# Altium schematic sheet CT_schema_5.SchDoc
size 479 x 328 mm
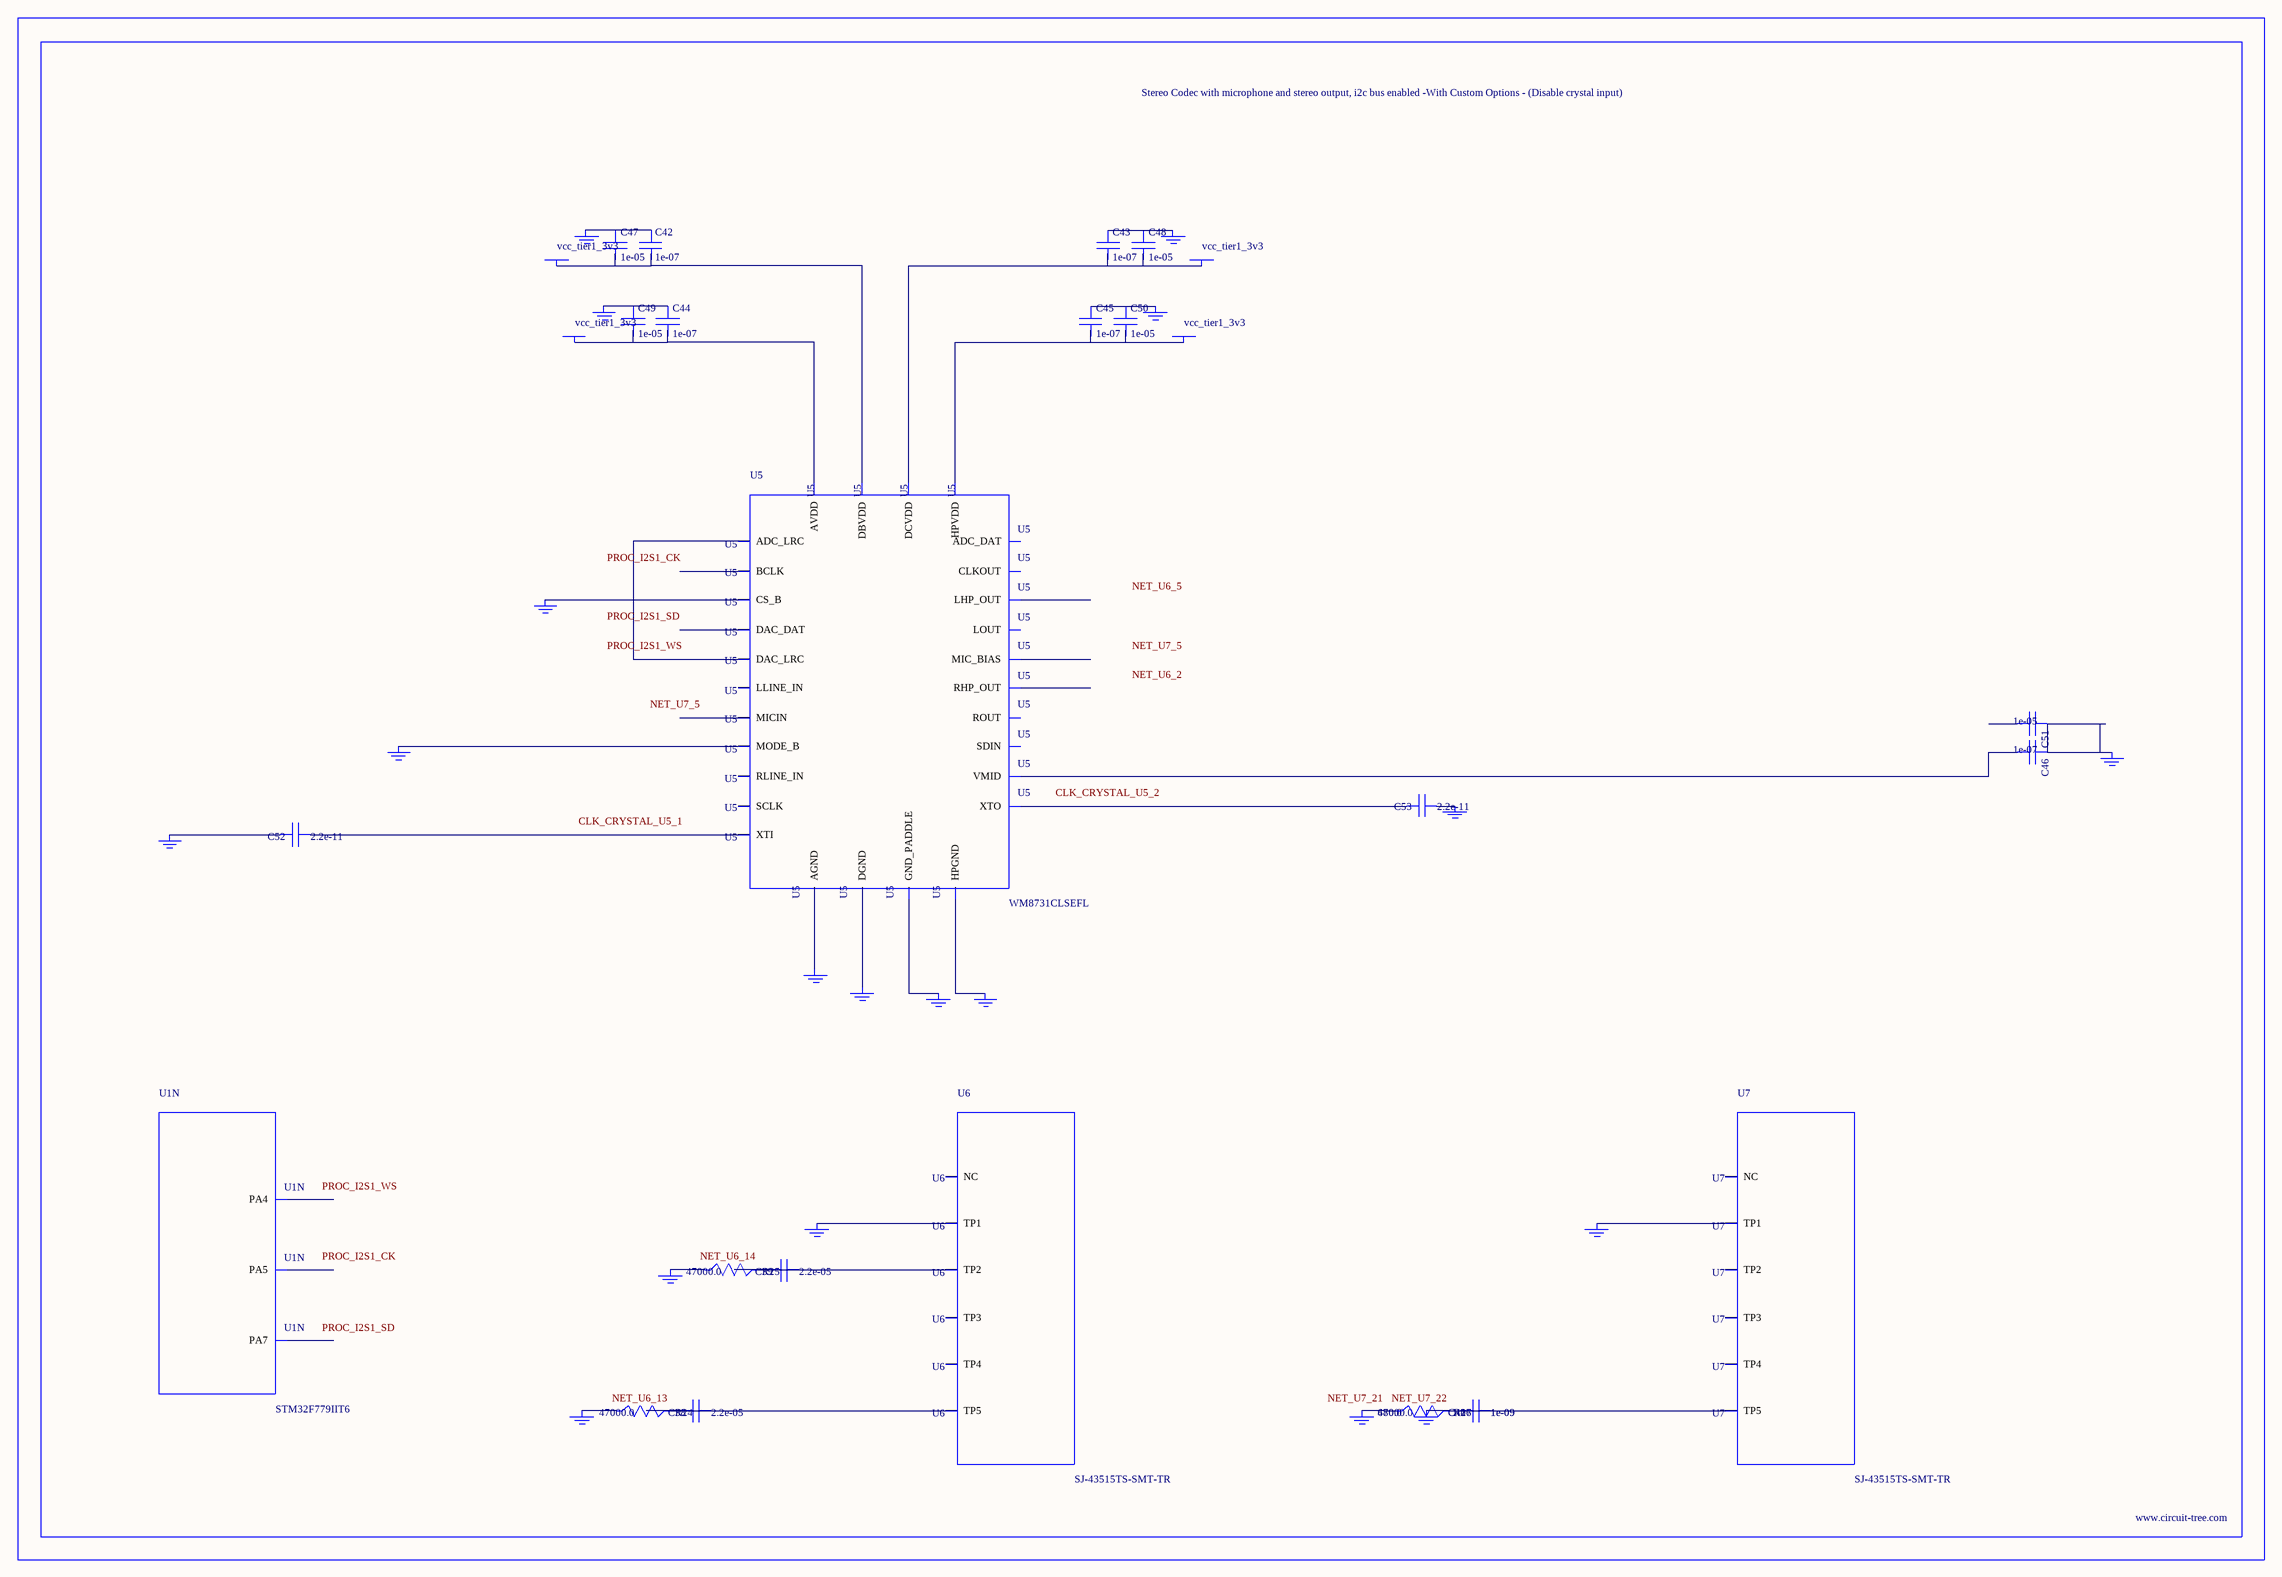
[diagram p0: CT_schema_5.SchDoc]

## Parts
BORDER4  (no value)
C38  2.2e-05  [C1210]
C39  2.2e-05  [C1210]
C40  1e-09  [C0402]
C41  1e-09  [C0402]
C42  1e-07  [C0402]
C43  1e-07  [C0402]
C44  1e-07  [C0402]
C45  1e-07  [C0402]
C46  1e-07  [C0402]
C47  1e-05  [C0805]
C48  1e-05  [C0805]
C49  1e-05  [C0805]
C50  1e-05  [C0805]
C51  1e-05  [C0805]
C52  2.2e-11  [C0402]
C53  2.2e-11  [C0402]
GND_INSTANCE_4_0  (no value)
GND_INSTANCE_4_1  (no value)
GND_INSTANCE_4_2  (no value)
GND_INSTANCE_4_3  (no value)
GND_INSTANCE_4_4  (no value)
GND_INSTANCE_4_5  (no value)
GND_INSTANCE_4_6  (no value)
GND_INSTANCE_4_7  (no value)
GND_INSTANCE_4_8  (no value)
GND_INSTANCE_4_9  (no value)
GND_INSTANCE_4_10  (no value)
GND_INSTANCE_4_11  (no value)
GND_INSTANCE_4_12  (no value)
GND_INSTANCE_4_13  (no value)
GND_INSTANCE_4_14  (no value)
GND_INSTANCE_4_15  (no value)
GND_INSTANCE_4_16  (no value)
GND_INSTANCE_4_17  (no value)
GND_INSTANCE_4_18  (no value)
POWER_INSTANCE_4_0  vcc_tier1_3v3
POWER_INSTANCE_4_1  vcc_tier1_3v3
POWER_INSTANCE_4_2  vcc_tier1_3v3
POWER_INSTANCE_4_3  vcc_tier1_3v3
R24  47000.0  [R0603]
R25  47000.0  [R0603]
R26  47000.0  [R0603]
R27  680.0  [R0603]
U1  STM32F779IIT6  [LQFP176]  (part N of 14)
U5  WM8731CLSEFL  [QFN-28]
U6  SJ-43515TS-SMT-TR  [SJ-43515TS-SMT-TR]
U7  SJ-43515TS-SMT-TR  [SJ-43515TS-SMT-TR]

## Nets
NetC38_1: C38.1 C38.2 R24.2 U6.5(TP5)
NetC39_1: C39.1 C39.2 R25.2 U6.2(TP2)
NetC40_1: C40.1 C40.2 C41.1 C41.2 GND_INSTANCE_4_18.0(GND) R26.2 R27.2 U7.5(TP5)
NetC42_1: C42.1 C47.1 GND_INSTANCE_4_3.0(GND)
NetC42_2: C42.2 C47.2 POWER_INSTANCE_4_1.0(PWR) U5.5(DBVDD)
NetC43_1: C43.1 C48.1 GND_INSTANCE_4_2.0(GND)
NetC43_2: C43.2 C48.2 POWER_INSTANCE_4_0.0(PWR) U5.3(DCVDD)
NetC44_1: C44.1 C49.1 GND_INSTANCE_4_6.0(GND)
NetC44_2: C44.2 C49.2 POWER_INSTANCE_4_3.0(PWR) U5.18(AVDD)
NetC45_1: C45.1 C50.1 GND_INSTANCE_4_4.0(GND)
NetC45_2: C45.2 C50.2 POWER_INSTANCE_4_2.0(PWR) U5.12(HPVDD)
NetC46_1: C46.1 C51.1 GND_INSTANCE_4_7.0(GND)
NetC46_2: C46.2 U5.20(VMID)
NetC52_1: C52.1 U5.1(XTI)
NetC52_2: C52.2 GND_INSTANCE_4_0.0(GND)
NetC53_1: C53.1 GND_INSTANCE_4_1.0(GND)
NetC53_2: C53.2 U5.2(XTO)
NetGND_INSTANCE_4_5_0: GND_INSTANCE_4_5.0(GND) U5.15(HPGND)
NetGND_INSTANCE_4_8_0: GND_INSTANCE_4_8.0(GND) U5.25(MODE_B)
NetGND_INSTANCE_4_9_0: GND_INSTANCE_4_9.0(GND) U5.26(CS_B)
NetGND_INSTANCE_4_10_0: GND_INSTANCE_4_10.0(GND) U5.29(GND_PADDLE)
NetGND_INSTANCE_4_11_0: GND_INSTANCE_4_11.0(GND) U5.4(DGND)
NetGND_INSTANCE_4_12_0: GND_INSTANCE_4_12.0(GND) U5.19(AGND)
NetGND_INSTANCE_4_13_0: GND_INSTANCE_4_13.0(GND) U6.1(TP1)
NetGND_INSTANCE_4_14_0: GND_INSTANCE_4_14.0(GND) R25.1
NetGND_INSTANCE_4_15_0: GND_INSTANCE_4_15.0(GND) R24.1
NetGND_INSTANCE_4_16_0: GND_INSTANCE_4_16.0(GND) U7.1(TP1)
NetGND_INSTANCE_4_17_0: GND_INSTANCE_4_17.0(GND) R26.1 R27.1
NetU5_9: U5.9(DAC_LRC) U5.11(ADC_LRC)

Not connected (* = marked no-connect by the designer): C51 2; U1 50(PA4) 51(PA5) 53(PA7); U5 6(CLKOUT) 7(BCLK) 8(DAC_DAT) 10(ADC_DAT) 13(LHP_OUT) 14(RHP_OUT) 16(LOUT) 17(ROUT) 21(MIC_BIAS) 22(MICIN) 23(RLINE_IN) 24(LLINE_IN) 27(SDIN) 28(SCLK); U6 3(TP3) 4(TP4) 6(NC); U7 2(TP2) 3(TP3) 4(TP4) 6(NC)

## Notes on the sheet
- Labels drawn without touching a wire or pin: CLK_CRYSTAL_U5_1, CLK_CRYSTAL_U5_2, NET_U6_2, NET_U6_5, NET_U6_13, NET_U6_14, NET_U7_5, NET_U7_21, NET_U7_22, PROC_I2S1_CK, PROC_I2S1_SD, PROC_I2S1_WS

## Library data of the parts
BORDER4 = BORDER_PAGE4
C38 C39 = C1210C224K5RACTU
C40 C41 = C0402C102K3RAC
C42-C46 = C0402C104K3RACTU
C47-C51 = C0805C106K8RACTU
C52 C53 = C0402C220K3RAC
GND_INSTANCE_4_0-GND_INSTANCE_4_18 = GND
POWER_INSTANCE_4_0-POWER_INSTANCE_4_3 = PWR
R24-R26 = RC0603JR-0747KL
R27 = RC0603JR-07680RL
